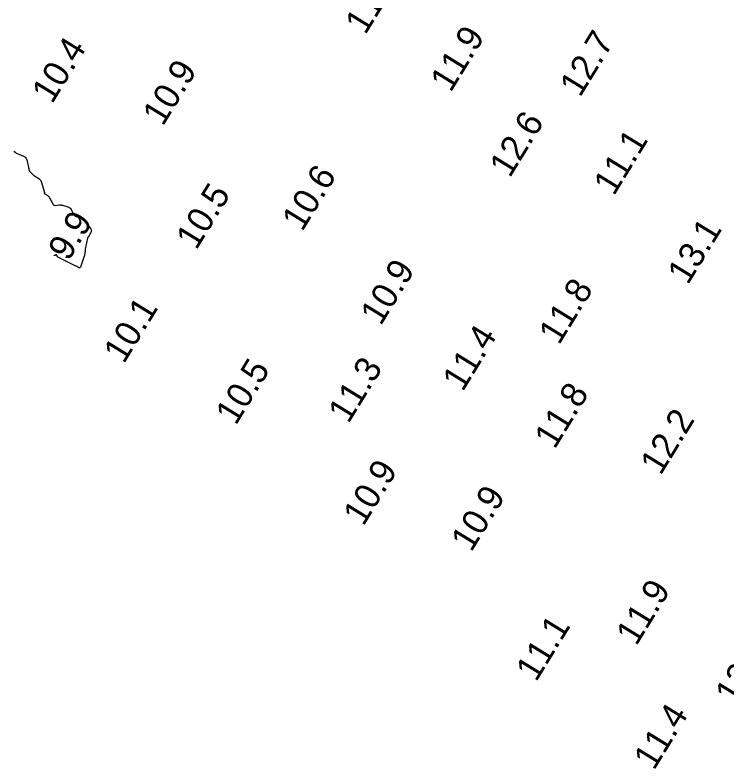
# Model space of a CAD drawing. Extents: x 1023796 to 1112670, y 656573 to 837340.
# Drawn here: x 1101182.7 to 1101321.7, y 687323.3 to 687470.4 of the extents above; entities that cross this region are included whole.
import ezdxf

# ---------------------------------------------------------------- set-up
doc = ezdxf.new("R2010")
doc.units = 0
doc.layers.add('V-CHAN-CONT-10FT', color=7, linetype='Continuous')
doc.layers.add('V-TOPO-SOUN', color=7, linetype='Continuous')

msp = doc.modelspace()

# ---------------------------------------------------------------- linework, layer by layer
at = {"layer": 'V-CHAN-CONT-10FT'}
msp.add_lwpolyline([(1101182.49, 687443.85), (1101182.73, 687443.62), (1101182.8, 687443.56), (1101182.86, 687443.51), (1101182.94, 687443.47), (1101183.01, 687443.43), (1101184.37, 687442.86), (1101184.6, 687442.73), (1101184.77, 687442.57), (1101184.9, 687442.37), (1101184.99, 687442.13), (1101185.32, 687440.68), (1101185.33, 687440.62), (1101185.35, 687440.56), (1101185.36, 687440.49), (1101185.37, 687440.43), (1101185.42, 687440.17), (1101185.43, 687440.11), (1101185.46, 687440.05), (1101185.49, 687440), (1101185.53, 687439.95), (1101186.04, 687439.4), (1101186.14, 687439.29), (1101186.25, 687439.2), (1101186.37, 687439.11), (1101186.49, 687439.03), (1101187.33, 687438.51), (1101187.5, 687438.39), (1101187.63, 687438.25), (1101187.74, 687438.08), (1101187.82, 687437.89), (1101188.48, 687435.76), (1101188.48, 687435.74), (1101188.48, 687435.73), (1101188.48, 687435.71), (1101188.46, 687435.7), (1101188.41, 687435.64), (1101188.4, 687435.63), (1101188.4, 687435.62), (1101188.4, 687435.6), (1101188.41, 687435.59), (1101189.08, 687435.15), (1101189.18, 687435.07), (1101189.28, 687434.98), (1101189.36, 687434.87), (1101189.43, 687434.75), (1101190.05, 687433.53), (1101190.14, 687433.4), (1101190.26, 687433.3), (1101190.4, 687433.26), (1101190.56, 687433.25), (1101191.27, 687433.33), (1101191.45, 687433.34), (1101191.62, 687433.34), (1101191.8, 687433.31), (1101191.97, 687433.27), (1101193.02, 687432.98), (1101193.23, 687432.9), (1101193.4, 687432.78), (1101193.55, 687432.63), (1101193.67, 687432.44), (1101194.12, 687431.51), (1101194.21, 687431.37), (1101194.32, 687431.26), (1101194.46, 687431.17), (1101194.62, 687431.11), (1101195.34, 687430.93), (1101195.48, 687430.89), (1101195.62, 687430.83), (1101195.74, 687430.75), (1101195.86, 687430.66), (1101196.42, 687430.17), (1101196.48, 687430.12), (1101196.53, 687430.05), (1101196.59, 687429.99), (1101196.63, 687429.91), (1101196.81, 687429.62), (1101196.86, 687429.55), (1101196.9, 687429.48), (1101196.95, 687429.4), (1101197, 687429.33), (1101197.49, 687428.67), (1101197.56, 687428.53), (1101197.6, 687428.39), (1101197.59, 687428.25), (1101197.54, 687428.1), (1101197.07, 687427.11), (1101197.06, 687427.09), (1101197.04, 687427.07), (1101197.02, 687427.05), (1101197, 687427.03), (1101196.89, 687426.97), (1101196.87, 687426.95), (1101196.85, 687426.93), (1101196.83, 687426.91), (1101196.83, 687426.88), (1101196.47, 687425.02), (1101196.44, 687424.88), (1101196.42, 687424.74), (1101196.4, 687424.6), (1101196.39, 687424.45), (1101196.34, 687423.88), (1101196.32, 687423.73), (1101196.29, 687423.59), (1101196.26, 687423.45), (1101196.21, 687423.32), (1101195.47, 687421.21), (1101195.42, 687421.12), (1101195.36, 687421.07), (1101195.27, 687421.06), (1101195.17, 687421.09), (1101194.74, 687421.31), (1101194.63, 687421.36), (1101194.52, 687421.42), (1101194.41, 687421.47), (1101194.31, 687421.52), (1101191.05, 687423.16), (1101191.01, 687423.19), (1101190.97, 687423.23), (1101190.94, 687423.27), (1101190.92, 687423.32), (1101190.86, 687423.55), (1101190.84, 687423.59), (1101190.82, 687423.61), (1101190.78, 687423.61), (1101190.75, 687423.6), (1101190.52, 687423.45), (1101190.51, 687423.45), (1101190.49, 687423.44), (1101190.48, 687423.44), (1101190.47, 687423.44), (1101190.41, 687423.45), (1101190.39, 687423.46), (1101190.38, 687423.46), (1101190.37, 687423.47), (1101190.36, 687423.47), (1101190.28, 687423.51)], dxfattribs=at)

# ---------------------------------------------------------------- texts
at = {"layer": 'V-TOPO-SOUN'}
for s, p in [('11.8 ', (1101251.08, 687466.38)), ('11.9 ', (1101267.72, 687455.13)), ('12.7 ', (1101292.98, 687454.18)), ('10.4 ', (1101189.93, 687452.9)), ('10.9 ', (1101211.55, 687448.53)), ('12.6 ', (1101279.27, 687438.46)), ('11.1 ', (1101299.58, 687434.95)), ('10.6 ', (1101238.75, 687427.99)), ('10.5 ', (1101218.08, 687424.38)), ('9.9', (1101193.11, 687422.18)), ('13.1 ', (1101314.01, 687417.57)), ('10.9 ', (1101254.07, 687409.59)), ('11.8 ', (1101288.88, 687405.85)), ('10.1 ', (1101203.94, 687402.18)), ('11.4 ', (1101270.08, 687396.73)), ('10.5 ', (1101225.79, 687390.16)), ('11.3 ', (1101247.77, 687390.49)), ('11.8 ', (1101288.03, 687385.51)), ('12.2 ', (1101308.7, 687380.39)), ('10.9 ', (1101250.69, 687370.48)), ('10.9 ', (1101271.75, 687365.43)), ('11.9 ', (1101303.97, 687347.12)), ('11.1 ', (1101284.42, 687340.11)), ('12.3 ', (1101323.3, 687335.54)), ('11.4 ', (1101307.42, 687322.84))]:
    msp.add_text(s, height=5, rotation=58.4285, dxfattribs=at).set_placement(p)

doc.saveas('drawing.dxf')
